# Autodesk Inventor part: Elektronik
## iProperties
Author: ketill
Created: 2002-11
Part Number: Elektronik
Material: Standard
Document SubType Name: Modellieren
Designer: ketill
Control State: 0
Master: False
Checked Out: False
PropertySet Name: Design Tracking Control
Shininess: 41.0
Angle Display Precision: 2
Document Length Units: 11269
Document Angle Units: 11283
Document Time Units: 11279
Document Mass Units: 11290
Document Length Units Precision: 3
Document Angle Units Precision: 2
Compacted: True
PropertySet Name: _Private Model Information
Density: 0.0
Volumn: 0.0
Area: 0.0
PropertySet Name: Model Information
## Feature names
1. Extrusion1
